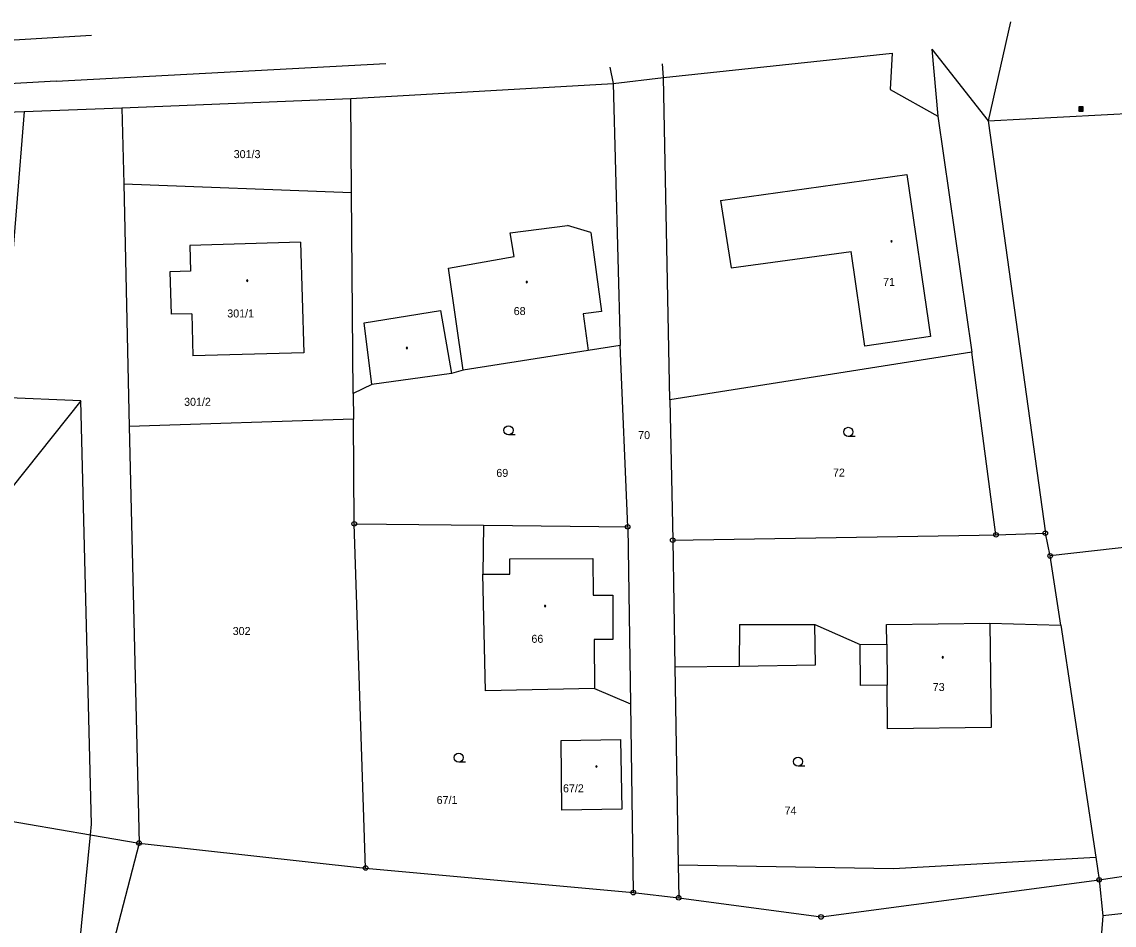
# Model space of a CAD drawing. Extents: x -454285 to -453563, y -1108687 to -1108249.
# Drawn here: x -453869.2 to -453773.6, y -1108414.3 to -1108335.3 of the extents above; entities that cross this region are included whole.
import ezdxf

# ---------------------------------------------------------------- set-up
doc = ezdxf.new("R2010")
doc.units = 0
for name, color, linetype in [('1', 7, 'Continuous'), ('14', 7, 'Continuous'), ('15', 7, 'Continuous'), ('2', 7, 'Continuous'), ('23', 7, 'Continuous'), ('25', 7, 'Continuous'), ('26', 7, 'Continuous'), ('28', 7, 'Continuous')]:
    doc.layers.add(name, color=color, linetype=linetype)

# ---------------------------------------------------------------- blocks, each defined once
blk = doc.blocks.new('Z402')
for start, end in [(0, 180), (180, 0)]:
    blk.add_arc((0, 0), 0.15, start, end)
blk = doc.blocks.new('Z105')
for radius in [0.5, 0.01]:
    blk.add_circle((0, 0), radius)
blk = doc.blocks.new('Z602')
for p, q in [((0.5, 0.5), (-0.5, 0.5)), ((-0.5, 0.5), (-0.5, -0.5)), ((0.3, 0.3), (-0.3, 0.3)), ((-0.3, 0.3), (-0.3, -0.1)), ((0.1, 0.1), (-0.2, 0.1)), ((0.1, -0.1), (0.1, 0.1)), ((0.3, -0.3), (0.3, 0.3)), ((0.5, -0.5), (0.5, 0.5)), ((-0.5, -0.5), (-0.3, -0.3)), ((-0.5, -0.5), (0.5, -0.5)), ((-0.3, -0.1), (0.1, -0.1)), ((-0.3, -0.3), (0.3, -0.3))]:
    blk.add_line(p, q)
blk = doc.blocks.new('Z3040')
blk.add_line((1.5, 0), (0, 0))
blk.add_circle((0, 1), 1)

msp = doc.modelspace()

# ---------------------------------------------------------------- linework, layer by layer
at = {"layer": '1'}
for p, q in [((-453782.707, -1108335.261), (-453784.667, -1108343.911)), ((-453813.067, -1108340.121), (-453793.057, -1108338.001)), ((-453789.607, -1108337.641), (-453789.067, -1108343.511)), ((-453789.607, -1108337.641), (-453784.667, -1108343.911)), ((-453840.417, -1108341.971), (-453817.467, -1108340.641)), ((-453817.467, -1108340.641), (-453813.067, -1108340.121)), ((-453817.467, -1108340.641), (-453816.877, -1108363.561)), ((-453812.507, -1108368.331), (-453813.067, -1108340.121)), ((-453860.457, -1108342.771), (-453840.417, -1108341.971)), ((-453840.357, -1108350.191), (-453840.417, -1108341.971)), ((-453869.017, -1108343.111), (-453860.457, -1108342.771)), ((-453860.457, -1108342.771), (-453860.297, -1108349.421)), ((-453899.577, -1108344.341), (-453869.017, -1108343.111)), ((-453869.017, -1108343.111), (-453871.027, -1108368.121)), ((-453789.067, -1108343.511), (-453786.097, -1108364.151)), ((-453784.667, -1108343.911), (-453767.907, -1108343.041)), ((-453784.667, -1108343.911), (-453779.667, -1108379.991)), ((-453860.297, -1108349.421), (-453859.807, -1108370.651)), ((-453860.297, -1108349.421), (-453840.357, -1108350.191)), ((-453840.217, -1108367.781), (-453840.357, -1108350.191)), ((-453844.827, -1108354.531), (-453854.527, -1108354.821)), ((-453854.527, -1108354.821), (-453854.457, -1108357.071)), ((-453844.827, -1108354.531), (-453844.537, -1108364.201)), ((-453854.457, -1108357.071), (-453856.257, -1108357.131)), ((-453856.257, -1108357.131), (-453856.147, -1108360.841)), ((-453854.347, -1108360.791), (-453856.147, -1108360.841)), ((-453854.347, -1108360.791), (-453854.247, -1108364.491)), ((-453816.877, -1108363.561), (-453819.657, -1108364.021)), ((-453816.207, -1108379.431), (-453816.877, -1108363.561)), ((-453844.537, -1108364.201), (-453854.247, -1108364.491)), ((-453819.657, -1108364.021), (-453830.607, -1108365.721)), ((-453786.097, -1108364.151), (-453812.507, -1108368.331)), ((-453783.987, -1108380.141), (-453786.097, -1108364.151)), ((-453830.607, -1108365.721), (-453831.607, -1108366.011)), ((-453831.607, -1108366.011), (-453838.597, -1108366.991)), ((-453838.597, -1108366.991), (-453840.217, -1108367.781)), ((-453840.217, -1108367.781), (-453840.197, -1108370.011)), ((-453864.037, -1108368.421), (-453876.247, -1108383.711)), ((-453863.107, -1108405.451), (-453864.037, -1108368.421)), ((-453812.507, -1108368.331), (-453812.267, -1108380.601)), ((-453840.197, -1108370.011), (-453859.807, -1108370.651)), ((-453859.807, -1108370.651), (-453858.957, -1108407.101)), ((-453840.127, -1108379.171), (-453840.197, -1108370.011)), ((-453840.127, -1108379.171), (-453828.807, -1108379.291)), ((-453839.137, -1108409.281), (-453840.127, -1108379.171)), ((-453828.807, -1108379.291), (-453828.887, -1108383.591)), ((-453828.807, -1108379.291), (-453816.207, -1108379.431)), ((-453816.207, -1108379.431), (-453815.967, -1108394.931)), ((-453812.267, -1108380.601), (-453785.457, -1108380.161)), ((-453785.457, -1108380.161), (-453783.987, -1108380.141)), ((-453779.247, -1108381.981), (-453779.667, -1108379.991)), ((-453812.267, -1108380.601), (-453812.087, -1108391.681)), ((-453767.107, -1108380.611), (-453779.247, -1108381.981)), ((-453778.327, -1108388.041), (-453779.247, -1108381.981)), ((-453828.637, -1108393.781), (-453828.887, -1108383.591)), ((-453784.517, -1108387.871), (-453784.397, -1108396.991)), ((-453784.517, -1108387.871), (-453778.327, -1108388.041)), ((-453799.787, -1108391.521), (-453799.837, -1108387.971)), ((-453799.837, -1108387.971), (-453795.877, -1108389.731)), ((-453778.327, -1108388.041), (-453775.257, -1108408.321)), ((-453795.847, -1108393.311), (-453795.877, -1108389.731)), ((-453812.087, -1108391.681), (-453806.447, -1108391.611)), ((-453812.087, -1108391.681), (-453811.797, -1108409.011)), ((-453806.447, -1108391.611), (-453799.787, -1108391.521)), ((-453819.117, -1108393.581), (-453828.637, -1108393.781)), ((-453819.117, -1108393.581), (-453815.967, -1108394.931)), ((-453793.507, -1108393.291), (-453795.847, -1108393.311)), ((-453793.467, -1108397.111), (-453793.507, -1108393.291)), ((-453815.967, -1108394.931), (-453815.717, -1108411.431)), ((-453922.357, -1108396.301), (-453863.197, -1108406.371)), ((-453784.397, -1108396.991), (-453793.467, -1108397.111)), ((-453822.017, -1108398.121), (-453816.827, -1108398.041)), ((-453821.967, -1108404.221), (-453822.017, -1108398.121)), ((-453816.827, -1108398.041), (-453816.727, -1108404.141)), ((-453816.727, -1108404.141), (-453821.967, -1108404.221)), ((-453863.197, -1108406.371), (-453863.107, -1108405.451)), ((-453863.197, -1108406.371), (-453858.957, -1108407.101)), ((-453774.957, -1108410.311), (-453747.537, -1108406.261)), ((-453858.957, -1108407.101), (-453865.887, -1108433.791)), ((-453858.957, -1108407.101), (-453839.137, -1108409.281)), ((-453775.257, -1108408.321), (-453774.957, -1108410.311)), ((-453839.137, -1108409.281), (-453815.717, -1108411.431)), ((-453811.797, -1108409.011), (-453811.747, -1108411.881)), ((-453799.287, -1108413.561), (-453774.957, -1108410.311)), ((-453774.957, -1108410.311), (-453774.627, -1108413.451)), ((-453815.717, -1108411.431), (-453811.747, -1108411.881)), ((-453811.747, -1108411.881), (-453799.287, -1108413.561)), ((-453774.627, -1108413.451), (-453775.707, -1108427.061))]:
    msp.add_line(p, q, dxfattribs=at)
at = {"layer": '2'}
for p, q in [((-453863.117, -1108336.461), (-453931.657, -1108340.511)), ((-453793.057, -1108338.001), (-453793.257, -1108341.181)), ((-453866.207, -1108340.441), (-453837.367, -1108338.911)), ((-453813.067, -1108340.121), (-453813.157, -1108338.931)), ((-453817.767, -1108339.211), (-453817.467, -1108340.641)), ((-453866.207, -1108340.441), (-453929.827, -1108344.131)), ((-453793.257, -1108341.181), (-453789.067, -1108343.511)), ((-453808.077, -1108350.881), (-453791.777, -1108348.611)), ((-453791.777, -1108348.611), (-453789.707, -1108362.781)), ((-453808.077, -1108350.881), (-453807.157, -1108356.771)), ((-453826.477, -1108353.721), (-453821.477, -1108353.081)), ((-453819.437, -1108353.701), (-453821.477, -1108353.081)), ((-453826.137, -1108355.801), (-453826.477, -1108353.721)), ((-453819.437, -1108353.701), (-453818.507, -1108360.591)), ((-453807.157, -1108356.771), (-453796.657, -1108355.361)), ((-453795.447, -1108363.621), (-453796.657, -1108355.361)), ((-453831.887, -1108356.811), (-453826.137, -1108355.801)), ((-453830.607, -1108365.721), (-453831.887, -1108356.811)), ((-453839.247, -1108361.601), (-453832.577, -1108360.501)), ((-453832.577, -1108360.501), (-453831.607, -1108366.011)), ((-453818.507, -1108360.591), (-453820.097, -1108360.801)), ((-453820.097, -1108360.801), (-453819.657, -1108364.021)), ((-453838.597, -1108366.991), (-453839.247, -1108361.601)), ((-453789.707, -1108362.781), (-453795.447, -1108363.621)), ((-453864.037, -1108368.421), (-453871.027, -1108368.121)), ((-453783.987, -1108380.141), (-453779.667, -1108379.991)), ((-453826.527, -1108382.241), (-453819.247, -1108382.211)), ((-453826.527, -1108383.581), (-453826.527, -1108382.241)), ((-453819.247, -1108382.211), (-453819.227, -1108385.411)), ((-453828.887, -1108383.591), (-453826.527, -1108383.581)), ((-453819.227, -1108385.411), (-453817.507, -1108385.401)), ((-453817.507, -1108385.401), (-453817.497, -1108389.291)), ((-453793.557, -1108387.991), (-453784.517, -1108387.871)), ((-453806.437, -1108387.991), (-453806.447, -1108391.611)), ((-453806.437, -1108387.991), (-453799.837, -1108387.971)), ((-453793.537, -1108389.711), (-453793.557, -1108387.991)), ((-453817.497, -1108389.291), (-453819.137, -1108389.291)), ((-453819.137, -1108389.291), (-453819.117, -1108393.581)), ((-453795.877, -1108389.731), (-453793.537, -1108389.711)), ((-453793.537, -1108389.711), (-453793.507, -1108393.291)), ((-453865.887, -1108433.791), (-453863.197, -1108406.371)), ((-453792.967, -1108409.311), (-453775.257, -1108408.321)), ((-453811.797, -1108409.011), (-453792.967, -1108409.311)), ((-453747.937, -1108410.651), (-453774.627, -1108413.451))]:
    msp.add_line(p, q, dxfattribs=at)

# ---------------------------------------------------------------- block references
at = {"layer": '23', "xscale": 0.4, "yscale": 0.4000000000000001}
for p in [(-453826.637, -1108371.391), (-453796.907, -1108371.531), (-453830.987, -1108400.021), (-453801.307, -1108400.371)]:
    msp.add_blockref('Z3040', p, dxfattribs=at)
at = {"layer": '25', "xscale": 0.4, "yscale": 0.4000000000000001}
for p in [(-453793.127, -1108354.451), (-453849.487, -1108357.901), (-453825.037, -1108358.031), (-453835.517, -1108363.791), (-453823.437, -1108386.371), (-453788.647, -1108390.851), (-453818.947, -1108400.401)]:
    msp.add_blockref('Z402', p, dxfattribs=at)
at = {"layer": '26', "xscale": 0.4, "yscale": 0.4000000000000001}
msp.add_blockref('Z602', (-453776.547, -1108342.881), dxfattribs=at)
at = {"layer": '28', "xscale": 0.4, "yscale": 0.4000000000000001}
for p in [(-453840.127, -1108379.171), (-453816.207, -1108379.431), (-453783.987, -1108380.141), (-453779.667, -1108379.991), (-453812.267, -1108380.601), (-453779.247, -1108381.981), (-453858.957, -1108407.101), (-453839.137, -1108409.281), (-453774.957, -1108410.311), (-453815.717, -1108411.431), (-453811.747, -1108411.881), (-453799.287, -1108413.561)]:
    msp.add_blockref('Z105', p, dxfattribs=at)

# ---------------------------------------------------------------- texts
at = {"layer": '14'}
for s, p in [('301/3', (-453850.675, -1108347.181)), ('301/2', (-453855.015, -1108368.851)), ('70', (-453815.292, -1108371.761)), ('69', (-453827.7, -1108375.071)), ('72', (-453798.25, -1108375.041)), ('302', (-453850.762, -1108388.901)), ('67/1', (-453832.923, -1108403.681)), ('74', (-453802.48, -1108404.601))]:
    msp.add_text(s, height=0.7, dxfattribs=at).set_placement(p)
at = {"layer": '15'}
for s, p in [('71', (-453793.863, -1108358.361)), ('301/1', (-453851.238, -1108361.121)), ('68', (-453826.18, -1108360.911)), ('66', (-453824.63, -1108389.581)), ('73', (-453789.52, -1108393.801)), ('67/2', (-453821.867, -1108402.661))]:
    msp.add_text(s, height=0.7, dxfattribs=at).set_placement(p)

doc.saveas('drawing.dxf')
